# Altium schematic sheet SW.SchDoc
size A4; DocumentNumber: 7; SheetNumber: 7; SheetTotal: 11; Abteilung: Hard/Software Entwicklung
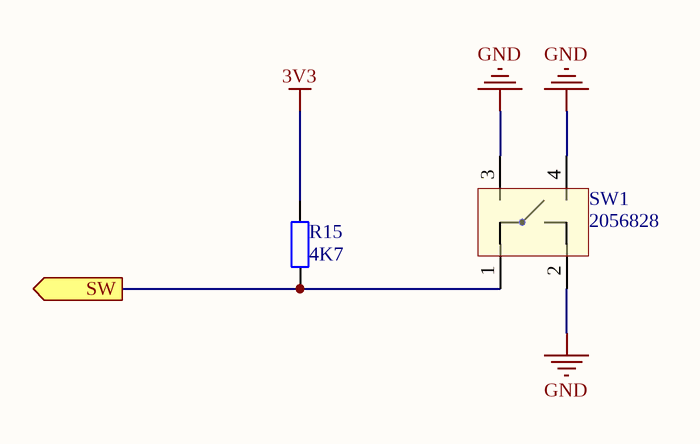
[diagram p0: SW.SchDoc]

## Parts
R15  4K7  [RLCDT_1206]
SW1  Supplier Part Number 1: 2056828  [SKHHLRA010]  (hidden comment: SKHHLRA010)

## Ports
SW (out)

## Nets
3V3: R15.2
GND: SW1.2 SW1.3 SW1.4
SW: R15.1 SW1.1 ; port SW

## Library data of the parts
R15 = R: Widerstand
SW1 = SW_SMD-Taster_90Grad: SWITCH, TACTILE, 6X6MM, HORIZ, GREY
